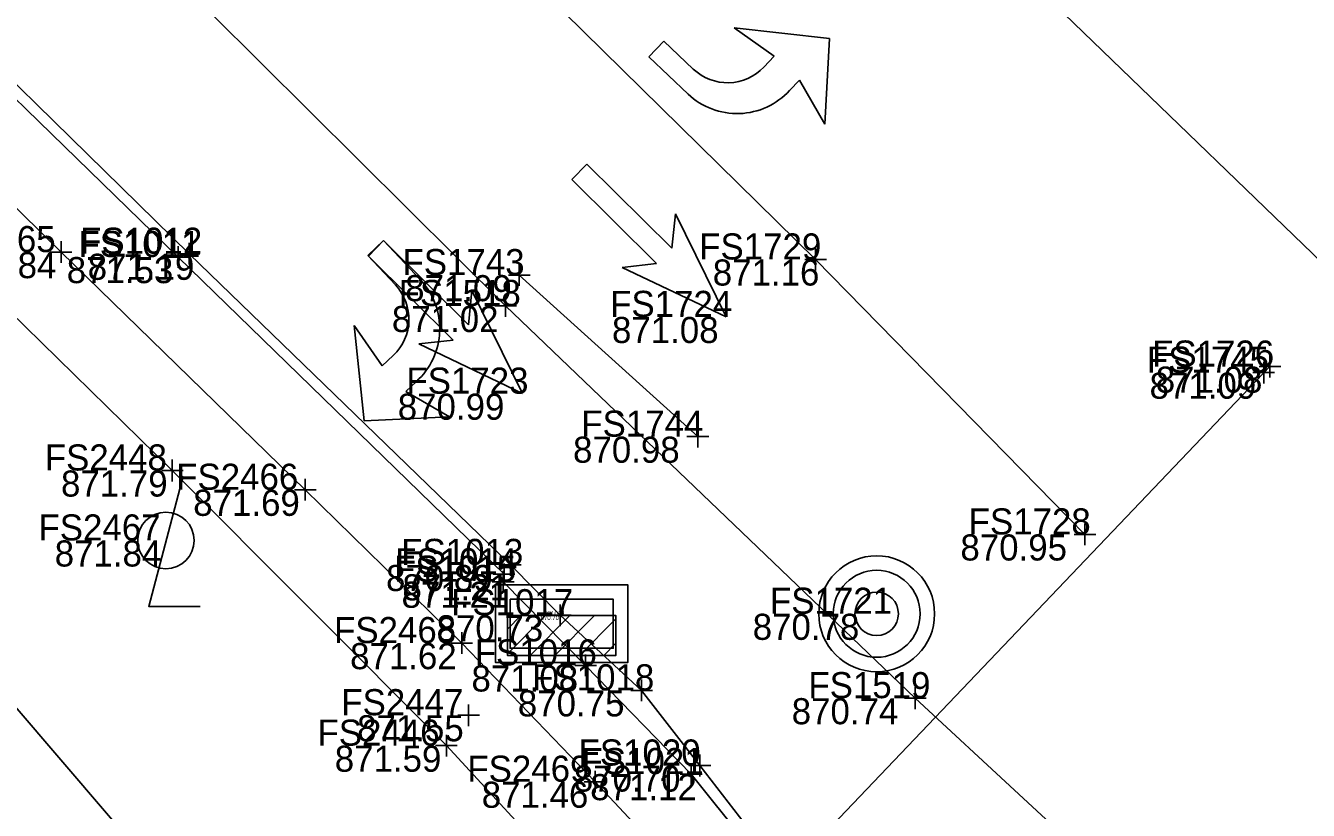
# Model space of a CAD drawing. Extents: x 1479420 to 1479833, y 379731 to 380103.
# Drawn here: x 1479533.9 to 1479593, y 379951.1 to 379987.2 of the extents above; entities that cross this region are included whole.
import ezdxf

# ---------------------------------------------------------------- set-up
doc = ezdxf.new("R2010")
doc.units = 0
for name, color, linetype in [('DR_X_Cells', 7, 'Continuous'), ('GK_Drainage_Nodes', 7, 'Continuous'), ('LT_X_Poles', 7, 'Continuous'), ('PM_X_Cells', 7, 'Continuous'), ('PM_X_Channelizing_Line', 7, 'Continuous'), ('PM_X_CL_Double_Solid', 7, 'Continuous'), ('PM_X_Lane_Line', 7, 'Continuous'), ('PM_X_Stop_Line', 7, 'Continuous'), ('PV_X_Curb', 7, 'Continuous'), ('PV_X_Walk', 7, 'Continuous'), ('SV_X_Break_Lines', 7, 'Continuous'), ('SV_X_Shot_Marker', 7, 'Continuous'), ('SV_X_Text_Elevation', 7, 'Continuous'), ('SV_X_Text_Name', 7, 'Continuous'), ('UT_X_Water', 7, 'Continuous')]:
    doc.layers.add(name, color=color, linetype=linetype)

msp = doc.modelspace()

# ---------------------------------------------------------------- linework, layer by layer
at = {"layer": 'DR_X_Cells'}
for p, q in [((1479556.084, 379958.313), (1479557.838, 379960.072)), ((1479556.084, 379959.446), (1479556.708, 379960.072)), ((1479557.14, 379958.239), (1479558.968, 379960.072)), ((1479558.269, 379958.239), (1479560.098, 379960.072)), ((1479559.399, 379958.239), (1479561.084, 379959.928)), ((1479560.529, 379958.239), (1479561.084, 379958.795))]:
    msp.add_line(p, q, dxfattribs=at)
for points in [[(1479555.542, 379961.49), (1479561.626, 379961.49), (1479561.626, 379957.906), (1479555.542, 379957.906)], [(1479556.209, 379960.822), (1479560.959, 379960.822), (1479560.959, 379958.572), (1479556.209, 379958.572)], [(1479556.084, 379960.072), (1479561.084, 379960.072), (1479561.084, 379958.239), (1479556.084, 379958.239)]]:
    msp.add_lwpolyline(points, close=True, dxfattribs=at)
for radius in [2.667, 2, 1]:
    msp.add_circle((1479573.085, 379960.155), radius, dxfattribs=at)
at = {"layer": 'GK_Drainage_Nodes'}
for p, q in [((1479573.085, 379962.155), (1479573.085, 379962.155)), ((1479558.584, 379961.489), (1479558.584, 379961.489)), ((1479558.584, 379960.822), (1479558.584, 379960.822)), ((1479556.209, 379959.697), (1479556.209, 379959.697)), ((1479558.584, 379960.072), (1479558.584, 379960.072)), ((1479558.584, 379960.072), (1479558.584, 379960.072)), ((1479558.584, 379959.697), (1479558.584, 379959.697)), ((1479560.959, 379959.697), (1479560.959, 379959.697)), ((1479573.085, 379960.155), (1479573.085, 379960.155)), ((1479573.085, 379960.155), (1479573.085, 379960.155)), ((1479573.085, 379960.155), (1479573.085, 379960.155)), ((1479558.584, 379958.572), (1479558.584, 379958.572)), ((1479558.584, 379957.906), (1479558.584, 379957.906)), ((1479573.085, 379958.155), (1479573.085, 379958.155))]:
    msp.add_line(p, q, dxfattribs=at)
msp.add_circle((1479573.085, 379960.155), 2, dxfattribs=at)
at = {"layer": 'LT_X_Poles'}
msp.add_lwpolyline([(1479541.156, 379966.482), (1479539.581, 379960.497), (1479541.944, 379960.497)], dxfattribs=at)
msp.add_circle((1479540.369, 379963.529), 1.3, dxfattribs=at)
at = {"layer": 'PM_X_Cells'}
for p, q in [((1479570.908, 379986.629), (1479566.519, 379987.116)), ((1479566.519, 379987.116), (1479568.373, 379985.817)), ((1479563.29, 379986.502), (1479562.602, 379985.777)), ((1479564.642, 379985.22), (1479563.29, 379986.502)), ((1479570.701, 379982.691), (1479570.908, 379986.629)), ((1479562.602, 379985.777), (1479564.401, 379984.071)), ((1479568.373, 379985.817), (1479567.89, 379985.307)), ((1479569.534, 379984.716), (1479570.701, 379982.691)), ((1479559.045, 379980.138), (1479559.748, 379980.849)), ((1479559.397, 379980.494), (1479559.397, 379980.494)), ((1479559.748, 379980.849), (1479563.66, 379976.983)), ((1479562.957, 379976.272), (1479559.045, 379980.138)), ((1479563.66, 379976.983), (1479563.818, 379978.565)), ((1479563.818, 379978.565), (1479566.153, 379973.815)), ((1479549.66, 379976.644), (1479550.39, 379977.328)), ((1479549.686, 379976.618), (1479550.39, 379977.328)), ((1479550.038, 379976.973), (1479550.038, 379976.973)), ((1479550.39, 379977.328), (1479554.295, 379973.455)), ((1479550.39, 379977.328), (1479552.084, 379975.519)), ((1479550.934, 379975.284), (1479549.66, 379976.644)), ((1479553.591, 379972.745), (1479549.686, 379976.618)), ((1479561.377, 379976.095), (1479562.957, 379976.272)), ((1479566.153, 379973.815), (1479561.377, 379976.095)), ((1479554.295, 379973.455), (1479554.456, 379975.037)), ((1479554.456, 379975.037), (1479556.784, 379970.284)), ((1479566.153, 379973.815), (1479566.153, 379973.815)), ((1479549.487, 379969.028), (1479549.027, 379973.42)), ((1479549.027, 379973.42), (1479550.315, 379971.557)), ((1479552.011, 379972.572), (1479553.591, 379972.745)), ((1479556.784, 379970.284), (1479552.011, 379972.572)), ((1479550.315, 379971.557), (1479550.828, 379972.038)), ((1479551.409, 379970.389), (1479553.427, 379969.211)), ((1479556.784, 379970.284), (1479556.784, 379970.284)), ((1479553.427, 379969.211), (1479549.487, 379969.028))]:
    msp.add_line(p, q, dxfattribs=at)
for points in [[(1479569.075, 379984.232), (1479569.075, 379984.232), (1479569.076, 379984.232), (1479569.534, 379984.716)], [(1479551.895, 379970.846), (1479551.895, 379970.846), (1479551.895, 379970.845), (1479551.409, 379970.389)]]:
    msp.add_lwpolyline(points, dxfattribs=at)
for centre, radius, start, end in [((1479566.223, 379986.887), 2.297, 226.52012, 316.52012), ((1479566.659, 379986.452), 3.281, 226.52012, 317.42861), ((1479549.257, 379973.714), 2.297, 313.13252, 43.13252), ((1479549.69, 379973.275), 3.281, 312.22403, 43.13252)]:
    msp.add_arc(centre, radius, start, end, dxfattribs=at)
at = {"layer": 'PM_X_Channelizing_Line'}
msp.add_lwpolyline([(1479582.673, 379963.806), (1479570.271, 379976.458), (1479548.912, 379997.457), (1479531.64, 380014.197), (1479515.852, 380030.017), (1479497.57, 380047.609), (1479484.703, 380060.356), (1479474.973, 380069.833)], dxfattribs=at)
at = {"layer": 'PM_X_CL_Double_Solid'}
msp.add_lwpolyline([(1479649.77, 379921.473), (1479632.094, 379938.759), (1479618.381, 379952.22), (1479598.438, 379971.627), (1479578.627, 379990.753), (1479560.467, 380008.345), (1479543.803, 380024.417)], dxfattribs=at)
at = {"layer": 'PM_X_Lane_Line'}
msp.add_line((1479556.633, 379975.739), (1479564.853, 379968.305), dxfattribs=at)
at = {"layer": 'PM_X_Stop_Line'}
msp.add_line((1479591.184, 379971.529), (1479569.966, 379949.291), dxfattribs=at)
at = {"layer": 'PV_X_Curb'}
for points in [[(1479465.43, 380051.173), (1479478.923, 380037.911), (1479495.631, 380021.426), (1479511.639, 380005.785), (1479526.613, 379991.238), (1479541.434, 379976.722), (1479556.225, 379962.402), (1479558.522, 379960.088), (1479562.263, 379956.631), (1479564.944, 379953.172), (1479567.55, 379949.792), (1479570.394, 379944.783), (1479571.863, 379941.541), (1479572.44, 379940.294), (1479572.888, 379938.328), (1479573.209, 379936.746), (1479573.486, 379935.414), (1479573.818, 379931.241), (1479573.756, 379927.245), (1479573.045, 379921.888), (1479571.771, 379917.234), (1479569.497, 379912.161), (1479567.166, 379908.643), (1479563.944, 379905.002)], [(1479465.217, 380050.646), (1479478.531, 380037.631), (1479495.524, 380020.938), (1479511.459, 380005.334), (1479526.353, 379990.752), (1479540.932, 379976.569), (1479555.934, 379961.972), (1479555.892, 379961.631), (1479559.685, 379957.777), (1479564.545, 379952.777), (1479567.017, 379949.687), (1479570.003, 379944.359), (1479571.368, 379941.515), (1479571.64, 379940.628), (1479572.403, 379938.2), (1479572.729, 379936.736), (1479572.917, 379935.416), (1479573.286, 379931.116), (1479573.281, 379927.358), (1479572.586, 379922.13), (1479571.403, 379917.504), (1479569.157, 379912.511), (1479566.948, 379909.055), (1479563.851, 379905.522)]]:
    msp.add_lwpolyline(points, dxfattribs=at)
at = {"layer": 'PV_X_Walk'}
for points in [[(1479459.693, 380050.631), (1479472.079, 380039.157), (1479482.634, 380028.96), (1479496.943, 380014.955), (1479511.111, 380000.888), (1479521.784, 379990.322), (1479535.54, 379976.798), (1479546.783, 379965.861), (1479553.984, 379958.805), (1479560.12, 379952.427), (1479566.081, 379946.058), (1479567.842, 379944.161), (1479569.592, 379942.392), (1479571.25, 379941.414)], [(1479571.225, 379941.406), (1479571.443, 379940.74), (1479572.055, 379938.942), (1479572.399, 379937.356), (1479572.583, 379936.247), (1479572.708, 379935.62), (1479569.085, 379935.113), (1479567.56, 379937.205), (1479566.035, 379939.554), (1479564.616, 379941.63), (1479559.488, 379947.364), (1479553.278, 379954.086), (1479540.659, 379966.748), (1479530.117, 379977.06), (1479515.964, 379990.896), (1479504.534, 380001.709), (1479490.824, 380015.396), (1479476.31, 380029.289), (1479463.443, 380042.077), (1479456.834, 380048.374)]]:
    msp.add_lwpolyline(points, dxfattribs=at)
at = {"layer": 'SV_X_Break_Lines'}
msp.add_lwpolyline([(1479534.387, 379905.648), (1479543.524, 379912.475), (1479551.336, 379918.185), (1479553.597, 379921.305), (1479553.861, 379925.501), (1479552.129, 379929.668), (1479547.926, 379935.993), (1479545.155, 379941.461), (1479539.822, 379948.42), (1479529.018, 379961.007), (1479520.635, 379970.728), (1479513.841, 379979.888), (1479504.809, 379988.776), (1479495.63, 379998.694), (1479487.89, 380006.933), (1479478.402, 380016.952), (1479472.872, 380022.536)], dxfattribs=at)
at = {"layer": 'SV_X_Shot_Marker'}
for p, q in [((1479535.04, 379976.798), (1479536.04, 379976.798)), ((1479535.54, 379977.298), (1479535.54, 379976.298)), ((1479535.54, 379976.798), (1479535.54, 379976.798)), ((1479540.932, 379977.069), (1479540.932, 379976.069)), ((1479541.434, 379977.222), (1479541.434, 379976.222)), ((1479570.271, 379976.958), (1479570.271, 379975.958)), ((1479540.432, 379976.569), (1479541.432, 379976.569)), ((1479540.932, 379976.569), (1479540.932, 379976.569)), ((1479540.934, 379976.722), (1479541.934, 379976.722)), ((1479541.434, 379976.722), (1479541.434, 379976.722)), ((1479556.633, 379976.239), (1479556.633, 379975.239)), ((1479569.771, 379976.458), (1479570.771, 379976.458)), ((1479570.271, 379976.458), (1479570.271, 379976.458)), ((1479556.133, 379975.739), (1479557.133, 379975.739)), ((1479556.633, 379975.739), (1479556.633, 379975.739)), ((1479556.003, 379974.819), (1479556.003, 379973.819)), ((1479555.503, 379974.319), (1479556.503, 379974.319)), ((1479556.003, 379974.319), (1479556.003, 379974.319)), ((1479590.684, 379971.529), (1479591.684, 379971.529)), ((1479590.899, 379971.751), (1479590.899, 379970.751)), ((1479591.184, 379972.029), (1479591.184, 379971.029)), ((1479591.184, 379971.529), (1479591.184, 379971.529)), ((1479590.399, 379971.251), (1479591.399, 379971.251)), ((1479590.899, 379971.251), (1479590.899, 379971.251)), ((1479564.853, 379968.805), (1479564.853, 379967.805)), ((1479564.353, 379968.305), (1479565.353, 379968.305)), ((1479564.853, 379968.305), (1479564.853, 379968.305)), ((1479540.159, 379966.748), (1479541.159, 379966.748)), ((1479540.659, 379967.248), (1479540.659, 379966.248)), ((1479540.659, 379966.748), (1479540.659, 379966.748)), ((1479546.783, 379966.361), (1479546.783, 379965.361)), ((1479546.283, 379965.861), (1479547.283, 379965.861)), ((1479546.783, 379965.861), (1479546.783, 379965.861)), ((1479582.173, 379963.806), (1479583.173, 379963.806)), ((1479582.673, 379964.306), (1479582.673, 379963.306)), ((1479582.673, 379963.806), (1479582.673, 379963.806)), ((1479556.225, 379962.902), (1479556.225, 379961.902)), ((1479555.725, 379962.402), (1479556.725, 379962.402)), ((1479555.892, 379962.131), (1479555.892, 379961.131)), ((1479555.934, 379962.472), (1479555.934, 379961.472)), ((1479556.225, 379962.402), (1479556.225, 379962.402)), ((1479555.392, 379961.631), (1479556.392, 379961.631)), ((1479555.434, 379961.972), (1479556.434, 379961.972)), ((1479555.892, 379961.631), (1479555.892, 379961.631)), ((1479555.934, 379961.972), (1479555.934, 379961.972)), ((1479558.522, 379960.588), (1479558.522, 379959.588)), ((1479558.022, 379960.088), (1479559.022, 379960.088)), ((1479558.522, 379960.088), (1479558.522, 379960.088)), ((1479553.984, 379959.305), (1479553.984, 379958.305)), ((1479553.484, 379958.805), (1479554.484, 379958.805)), ((1479553.984, 379958.805), (1479553.984, 379958.805)), ((1479559.685, 379958.277), (1479559.685, 379957.277)), ((1479559.185, 379957.777), (1479560.185, 379957.777)), ((1479559.685, 379957.777), (1479559.685, 379957.777)), ((1479562.263, 379957.131), (1479562.263, 379956.131)), ((1479574.861, 379956.771), (1479574.861, 379955.771)), ((1479561.763, 379956.631), (1479562.763, 379956.631)), ((1479562.263, 379956.631), (1479562.263, 379956.631)), ((1479574.361, 379956.271), (1479575.361, 379956.271)), ((1479574.861, 379956.271), (1479574.861, 379956.271)), ((1479554.298, 379955.987), (1479554.298, 379954.987)), ((1479553.798, 379955.487), (1479554.798, 379955.487)), ((1479554.298, 379955.487), (1479554.298, 379955.487)), ((1479553.278, 379954.586), (1479553.278, 379953.586)), ((1479552.778, 379954.086), (1479553.778, 379954.086)), ((1479553.278, 379954.086), (1479553.278, 379954.086)), ((1479564.444, 379953.172), (1479565.444, 379953.172)), ((1479564.545, 379953.277), (1479564.545, 379952.277)), ((1479564.944, 379953.672), (1479564.944, 379952.672)), ((1479564.944, 379953.172), (1479564.944, 379953.172)), ((1479560.12, 379952.927), (1479560.12, 379951.927)), ((1479564.045, 379952.777), (1479565.045, 379952.777)), ((1479564.545, 379952.777), (1479564.545, 379952.777)), ((1479559.62, 379952.427), (1479560.62, 379952.427)), ((1479560.12, 379952.427), (1479560.12, 379952.427))]:
    msp.add_line(p, q, dxfattribs=at)
at = {"layer": 'UT_X_Water'}
msp.add_lwpolyline([(1479473.217, 380054.881), (1479498.741, 380029.974), (1479514.505, 380014.086), (1479533.448, 379996.735), (1479556.003, 379974.319), (1479574.861, 379956.271), (1479584.403, 379947.432), (1479599.597, 379932.819), (1479630.106, 379903.783), (1479644.769, 379889.722), (1479654.209, 379882.356), (1479664.266, 379872.629), (1479692.509, 379845.847), (1479712.672, 379826.686), (1479730.739, 379809.85), (1479753.15, 379788.309), (1479771.842, 379770.542), (1479781.678, 379761.101)], dxfattribs=at)

# ---------------------------------------------------------------- texts
at = {"layer": 'SV_X_Text_Elevation'}
for s, height, p in [('871.84', 1.2, (1479530.42, 379975.598)), ('871.53', 1.2, (1479535.802, 379975.369)), ('871.19', 1.2, (1479536.768, 379975.522)), ('871.16', 1.2, (1479565.539, 379975.258)), ('871.09', 1.2, (1479551.38, 379974.539)), ('871.02', 1.2, (1479550.769, 379973.119)), ('871.08', 1.2, (1479560.9, 379972.615)), ('871.08', 1.2, (1479585.931, 379970.329)), ('871.09', 1.2, (1479585.646, 379970.051)), ('870.99', 1.2, (1479551.039, 379969.084)), ('870.98', 1.2, (1479559.108, 379967.105)), ('871.79', 1.2, (1479535.539, 379965.548)), ('871.69', 1.2, (1479541.625, 379964.661)), ('870.95', 1.2, (1479576.938, 379962.606)), ('871.84', 1.2, (1479535.249, 379962.329)), ('870.89', 1.2, (1479550.499, 379961.202)), ('871.21', 1.2, (1479551.215, 379960.431)), ('871.21', 1.2, (1479551.257, 379960.772)), ('870.73', 1.2, (1479552.825, 379958.888)), ('870.70', 0.2, (1479557.617, 379959.872)), ('870.78', 1.2, (1479567.378, 379958.955)), ('871.62', 1.2, (1479548.845, 379957.605)), ('871.08', 1.2, (1479554.432, 379956.577)), ('870.75', 1.2, (1479556.566, 379955.431)), ('870.74', 1.2, (1479569.173, 379955.071)), ('871.55', 1.2, (1479549.168, 379954.287)), ('871.59', 1.2, (1479548.139, 379952.886)), ('870.70', 1.2, (1479559.143, 379951.972)), ('871.12', 1.2, (1479559.898, 379951.577)), ('871.46', 1.2, (1479554.905, 379951.227))]:
    msp.add_text(s, height=height, dxfattribs=at).set_placement(p)
at = {"layer": 'SV_X_Text_Name'}
for s, height, p in [('FS2465', 1.2, (1479529.673, 379976.798)), ('FS1011', 1.2, (1479536.341, 379976.569)), ('FS1012', 1.2, (1479536.418, 379976.722)), ('FS1729', 1.2, (1479564.915, 379976.458)), ('FS1743', 1.2, (1479551.258, 379975.739)), ('FS1518', 1.2, (1479551.082, 379974.319)), ('FS1724', 1.2, (1479560.815, 379973.815)), ('FS1726', 1.2, (1479585.761, 379971.529)), ('FS1745', 1.2, (1479585.524, 379971.251)), ('FS1723', 1.2, (1479551.437, 379970.284)), ('FS1744', 1.2, (1479559.487, 379968.305)), ('FS2448', 1.2, (1479534.792, 379966.748)), ('FS2466', 1.2, (1479540.84, 379965.861)), ('FS1728', 1.2, (1479577.317, 379963.806)), ('FS2467', 1.2, (1479534.502, 379963.529)), ('FS1014', 1.2, (1479550.918, 379961.972)), ('FS1013', 1.2, (1479551.2, 379962.402)), ('FS1015', 1.2, (1479550.867, 379961.631)), ('FS1017', 1.2, (1479553.497, 379960.088)), ('FS1721', 1.2, (1479568.172, 379960.155)), ('FS1019', 0.2, (1479557.745, 379960.072)), ('FS2468', 1.2, (1479548.107, 379958.805)), ('FS1016', 1.2, (1479554.584, 379957.777)), ('FS1018', 1.2, (1479557.228, 379956.631)), ('FS1519', 1.2, (1479569.94, 379956.271)), ('FS2447', 1.2, (1479548.44, 379955.487)), ('FS2446', 1.2, (1479547.345, 379954.086)), ('FS1020', 1.2, (1479559.361, 379953.172)), ('FS1021', 1.2, (1479559.5, 379952.777)), ('FS2469', 1.2, (1479554.243, 379952.427))]:
    msp.add_text(s, height=height, dxfattribs=at).set_placement(p)

doc.saveas('drawing.dxf')
